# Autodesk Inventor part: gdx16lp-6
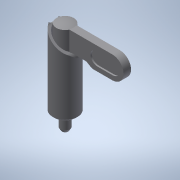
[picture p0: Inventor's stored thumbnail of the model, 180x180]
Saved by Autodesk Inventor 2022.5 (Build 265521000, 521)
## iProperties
Created: 2016-12
Part Number: gdx16lp-6
Material: 一般
Document SubType Name: Modeling
Designer: imaocorp
Density: 1 g/cm^3
Appearance: 既定
Author: imaocorp
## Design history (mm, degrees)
node "gdx16lp-6.x_t1"
node "gdx16lp-6"
node "Base1"
